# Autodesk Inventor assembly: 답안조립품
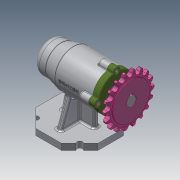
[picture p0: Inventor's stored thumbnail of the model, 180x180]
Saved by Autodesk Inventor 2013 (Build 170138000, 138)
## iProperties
Created: 2021-01
Part Number: 답안조립품
Document SubType Name: Assembly
Designer: 19
Author: 19
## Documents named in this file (12)
- C:\Users\user\Desktop\710106V1004\답안조립품.iam
- C:\Users\user\Desktop\710106V1004\본체.ipt
- C:\Users\user\Desktop\710106V1004\멈춤나사 M3.ipt
- C:\Users\user\Desktop\710106V1004\베어링 6004.ipt
- C:\Users\user\Desktop\710106V1004\베어링 51202.ipt
- C:\Users\user\Desktop\710106V1004\볼트 M4.ipt
- C:\Users\user\Desktop\710106V1004\스프로킷.ipt
- C:\Users\user\Desktop\710106V1004\어댑터슬리브.ipt
- C:\Users\user\Desktop\710106V1004\오일 실.ipt
- C:\Users\user\Desktop\710106V1004\축.ipt
- C:\Users\user\Desktop\710106V1004\커버.ipt
- C:\Users\user\Desktop\710106V1004\키 5 x 5 x 14.ipt
